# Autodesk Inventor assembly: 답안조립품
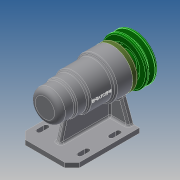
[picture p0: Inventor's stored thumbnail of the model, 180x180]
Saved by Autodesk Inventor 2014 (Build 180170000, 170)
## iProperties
Created: 2017-09
Part Number: 답안조립품
Document SubType Name: Assembly
Designer: kb542-00
Author: kb542-00
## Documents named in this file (12)
- C:\Users\kb542-00\Desktop\470907V1020\답안조립품.iam
- C:\Users\kb542-00\Desktop\470907V1020\1-본체.ipt
- C:\Users\kb542-00\Desktop\470907V1020\축.ipt
- C:\Users\kb542-00\Desktop\470907V1020\키 5 x 5 x 16.ipt
- C:\Users\kb542-00\Desktop\470907V1020\베어링 6004.ipt
- C:\Users\kb542-00\Desktop\470907V1020\오일 실 20x35x7.ipt
- C:\Users\kb542-00\Desktop\470907V1020\커버.ipt
- C:\Users\kb542-00\Desktop\470907V1020\베어링 51202.ipt
- C:\Users\kb542-00\Desktop\470907V1020\어댑터슬리브.ipt
- C:\Users\kb542-00\Desktop\470907V1020\볼트 M4 x 12.ipt
- C:\Users\kb542-00\Desktop\470907V1020\V벨트풀리.ipt
- C:\Users\kb542-00\Desktop\470907V1020\멈춤나사 M3x8.ipt
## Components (2 placed, 2 different names)
1. 1-본체:1
2. V벨트풀리:1
